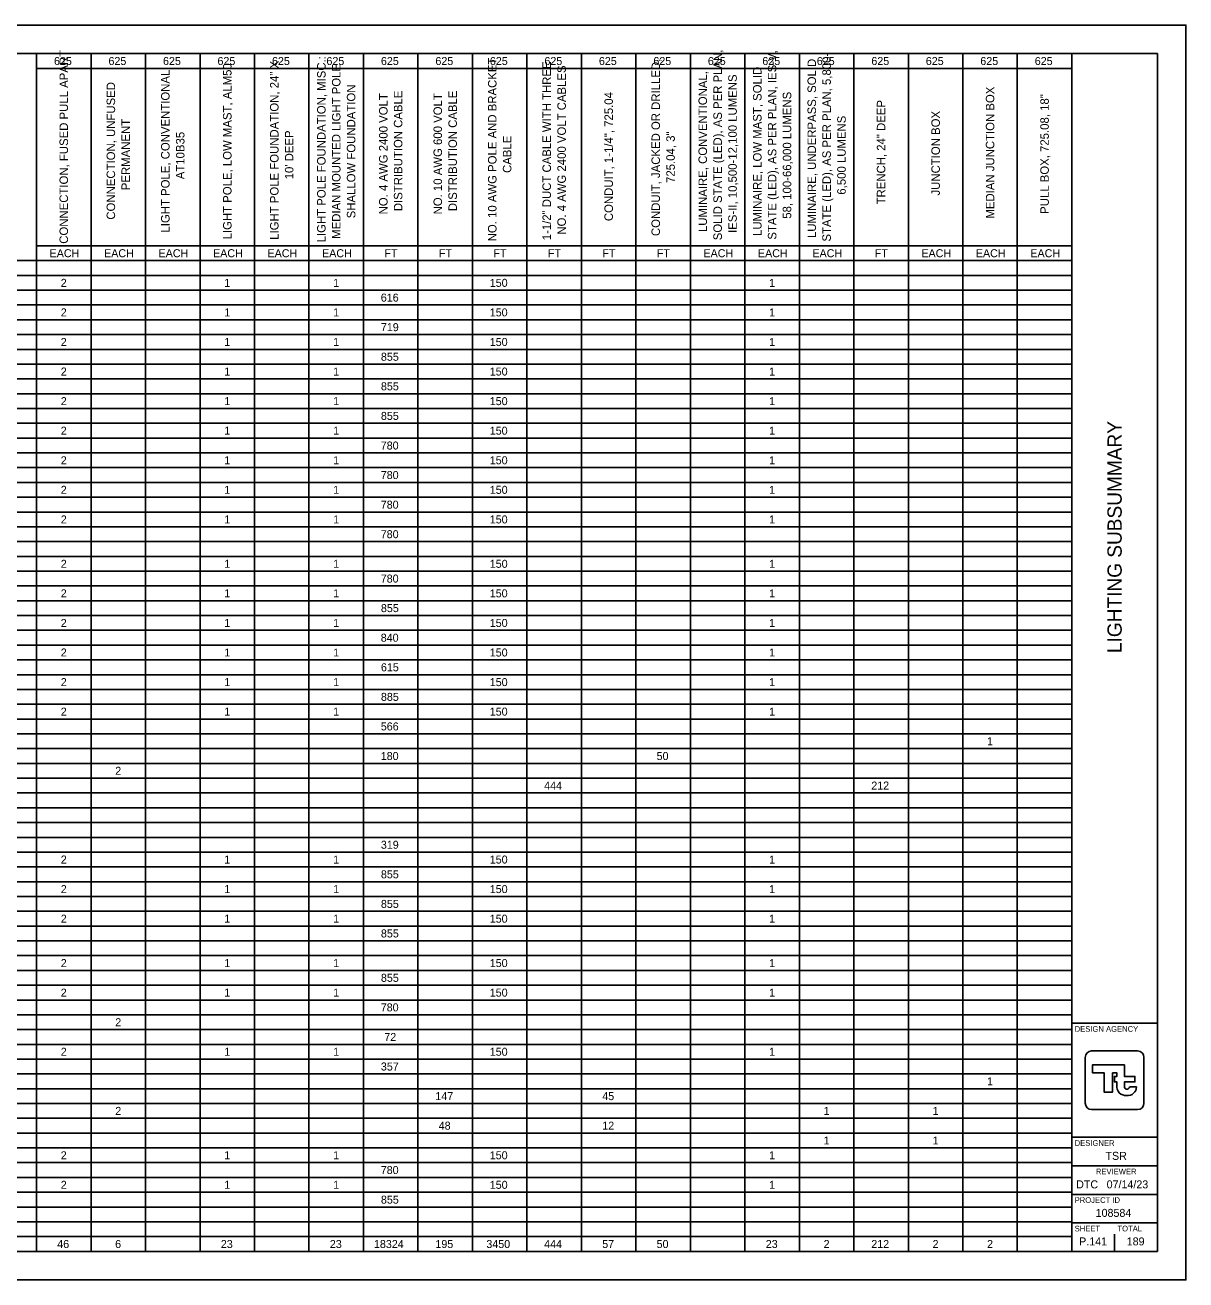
# Model space of a CAD drawing. Extents: x 0 to 34, y 0 to 22.
# Drawn here: x 13.65 to 34, y 0 to 22 of the extents above; entities that cross this region are included whole.
import ezdxf

# ---------------------------------------------------------------- set-up
doc = ezdxf.new("R2010")
doc.units = 0
for name, color, linetype in [('Default', 7, 'Continuous'), ('SH_Border', 7, 'Continuous'), ('SH_Cut_Line', 7, 'Continuous'), ('SH_Data', 7, 'Continuous')]:
    doc.layers.add(name, color=color, linetype=linetype)

msp = doc.modelspace()

# ---------------------------------------------------------------- linework, layer by layer
at = {"layer": 'Default'}
for p, q in [((1.5, 21.5), (32, 21.5)), ((13.852, 21.5), (13.852, 0.5)), ((14.807, 21.5), (14.807, 0.759)), ((15.762, 21.5), (15.762, 0.759)), ((16.718, 21.5), (16.718, 0.759)), ((17.673, 21.5), (17.673, 0.759)), ((18.628, 21.5), (18.628, 0.759)), ((19.583, 21.5), (19.583, 0.759)), ((20.538, 21.5), (20.538, 0.759)), ((21.493, 21.5), (21.493, 0.759)), ((22.449, 21.5), (22.449, 0.759)), ((23.404, 21.5), (23.404, 0.759)), ((24.359, 21.5), (24.359, 0.759)), ((25.314, 21.5), (25.314, 0.759)), ((26.269, 21.5), (26.269, 0.759)), ((27.224, 21.5), (27.224, 0.759)), ((28.179, 21.5), (28.179, 0.759)), ((29.135, 21.5), (29.135, 0.759)), ((30.09, 21.5), (30.09, 0.759)), ((31.045, 21.5), (31.045, 0.759)), ((32, 21.5), (32, 0.759)), ((13.852, 21.241), (32, 21.241)), ((13.852, 18.13), (32, 18.13)), ((1.5, 17.87), (32, 17.87)), ((1.5, 17.611), (32, 17.611)), ((1.5, 17.352), (32, 17.352)), ((1.5, 17.093), (32, 17.093)), ((1.5, 16.833), (32, 16.833)), ((1.5, 16.574), (32, 16.574)), ((1.5, 16.315), (32, 16.315)), ((1.5, 16.056), (32, 16.056)), ((1.5, 15.796), (32, 15.796)), ((1.5, 15.537), (32, 15.537)), ((1.5, 15.278), (32, 15.278)), ((1.5, 15.019), (32, 15.019)), ((1.5, 14.759), (32, 14.759)), ((1.5, 14.5), (32, 14.5)), ((1.5, 14.241), (32, 14.241)), ((1.5, 13.981), (32, 13.981)), ((1.5, 13.722), (32, 13.722)), ((1.5, 13.463), (32, 13.463)), ((1.5, 13.204), (32, 13.204)), ((1.5, 12.944), (32, 12.944)), ((1.5, 12.685), (32, 12.685)), ((1.5, 12.426), (32, 12.426)), ((1.5, 12.167), (32, 12.167)), ((1.5, 11.907), (32, 11.907)), ((1.5, 11.648), (32, 11.648)), ((1.5, 11.389), (32, 11.389)), ((1.5, 11.13), (32, 11.13)), ((1.5, 10.87), (32, 10.87)), ((1.5, 10.611), (32, 10.611)), ((1.5, 10.352), (32, 10.352)), ((1.5, 10.093), (32, 10.093)), ((1.5, 9.833), (32, 9.833)), ((1.5, 9.574), (32, 9.574)), ((1.5, 9.315), (32, 9.315)), ((1.5, 9.056), (32, 9.056)), ((1.5, 8.796), (32, 8.796)), ((1.5, 8.537), (32, 8.537)), ((1.5, 8.278), (32, 8.278)), ((1.5, 8.019), (32, 8.019)), ((1.5, 7.759), (32, 7.759)), ((1.5, 7.5), (32, 7.5)), ((1.5, 7.241), (32, 7.241)), ((1.5, 6.981), (32, 6.981)), ((1.5, 6.722), (32, 6.722)), ((1.5, 6.463), (32, 6.463)), ((1.5, 6.204), (32, 6.204)), ((1.5, 5.944), (32, 5.944)), ((1.5, 5.685), (32, 5.685)), ((1.5, 5.426), (32, 5.426)), ((1.5, 5.167), (32, 5.167)), ((1.5, 4.907), (32, 4.907)), ((1.5, 4.648), (32, 4.648)), ((1.5, 4.389), (32, 4.389)), ((1.5, 4.13), (32, 4.13)), ((1.5, 3.87), (32, 3.87)), ((1.5, 3.611), (32, 3.611)), ((1.5, 3.352), (32, 3.352)), ((1.5, 3.093), (32, 3.093)), ((1.5, 2.833), (32, 2.833)), ((1.5, 2.574), (32, 2.574)), ((1.5, 2.315), (32, 2.315)), ((1.5, 2.056), (32, 2.056)), ((1.5, 1.796), (32, 1.796)), ((1.5, 1.537), (32, 1.537)), ((1.5, 1.278), (32, 1.278)), ((1.5, 1.019), (32, 1.019)), ((1.5, 0.759), (32, 0.759)), ((14.807, 0.759), (14.807, 0.5)), ((15.762, 0.759), (15.762, 0.5)), ((16.718, 0.759), (16.718, 0.5)), ((17.673, 0.759), (17.673, 0.5)), ((18.628, 0.759), (18.628, 0.5)), ((19.583, 0.759), (19.583, 0.5)), ((20.538, 0.759), (20.538, 0.5)), ((21.493, 0.759), (21.493, 0.5)), ((22.449, 0.759), (22.449, 0.5)), ((23.404, 0.759), (23.404, 0.5)), ((24.359, 0.759), (24.359, 0.5)), ((25.314, 0.759), (25.314, 0.5)), ((26.269, 0.759), (26.269, 0.5)), ((27.224, 0.759), (27.224, 0.5)), ((28.179, 0.759), (28.179, 0.5)), ((29.135, 0.759), (29.135, 0.5)), ((30.09, 0.759), (30.09, 0.5)), ((31.045, 0.759), (31.045, 0.5)), ((32, 0.759), (32, 0.5)), ((1.5, 0.5), (32, 0.5))]:
    msp.add_line(p, q, dxfattribs=at)
at = {"layer": 'SH_Border'}
for p, q in [((32, 0.5), (32, 21.5)), ((32, 4.5), (33.5, 4.5)), ((32, 2.5), (33.5, 2.5)), ((32, 2), (33.5, 2)), ((32, 1.5), (33.5, 1.5)), ((32, 1), (33.5, 1))]:
    msp.add_line(p, q, dxfattribs=at)
msp.add_lwpolyline([(1.5, 21.5), (33.5, 21.5), (33.5, 0.5), (1.5, 0.5)], close=True, dxfattribs=at)
at = {"layer": 'SH_Cut_Line'}
msp.add_lwpolyline([(0, 0), (34, 0), (34, 22), (0, 22)], close=True, dxfattribs=at)
at = {"layer": 'SH_Data'}
for p, q in [((32.75, 3.5), (32.75, 3.5)), ((32.791, 3.415), (32.791, 3.415)), ((33.136, 3.385), (33.015, 3.385)), ((32.375, 0.675), (32.375, 0.675)), ((32.75, 0.5), (32.75, 0.8))]:
    msp.add_line(p, q, dxfattribs=at)
for points in [[(32.348, 4.014), (33.152, 4.014)], [(32.236, 3.099), (32.236, 3.901)], [(32.922, 3.399), (32.922, 3.47), (33.107, 3.47), (33.107, 3.568), (32.922, 3.568), (32.922, 3.768), (32.361, 3.768), (32.361, 3.632), (32.566, 3.632), (32.566, 3.294), (32.715, 3.294), (32.715, 3.63), (32.79, 3.63), (32.79, 3.568), (32.748, 3.568), (32.748, 3.47), (32.79, 3.47), (32.79, 3.415), (32.791, 3.415)], [(33.264, 3.901), (33.264, 3.099)], [(33.152, 2.986), (32.348, 2.986)]]:
    msp.add_lwpolyline(points, dxfattribs=at)
for centre, radius, start, end in [((32.348, 3.901), 0.113, 90, 180), ((33.152, 3.901), 0.113, 360, 90), ((32.949, 3.392), 0.16, 171.8856, 274.8323), ((32.968, 3.392), 0.0473, 171.8856, 350.9243), ((32.976, 3.392), 0.16, 265.1677, 357.3201), ((32.348, 3.099), 0.113, 180, 270), ((33.152, 3.099), 0.113, 270, 360)]:
    msp.add_arc(centre, radius, start, end, dxfattribs=at)

# ---------------------------------------------------------------- texts
at = {"layer": 'Default'}
for s, height, p in [('625', 0.1403, (14.158, 21.3)), ('625', 0.1403, (15.113, 21.3)), ('625', 0.1403, (16.069, 21.3)), ('625', 0.1403, (17.024, 21.3)), ('625', 0.1403, (17.979, 21.3)), ('625', 0.1403, (18.934, 21.3)), ('625', 0.1403, (19.889, 21.3)), ('625', 0.1403, (20.844, 21.3)), ('625', 0.1403, (21.799, 21.3)), ('625', 0.1403, (22.755, 21.3)), ('625', 0.1403, (23.71, 21.3)), ('625', 0.1403, (24.665, 21.3)), ('625', 0.1403, (25.62, 21.3)), ('625', 0.1403, (26.575, 21.3)), ('625', 0.1403, (27.53, 21.3)), ('625', 0.1403, (28.486, 21.3)), ('625', 0.1403, (29.441, 21.3)), ('625', 0.1403, (30.396, 21.3)), ('625', 0.1403, (31.351, 21.3)), ('EACH', 0.1403, (14.081, 17.93)), ('EACH', 0.1403, (15.036, 17.93)), ('EACH', 0.1403, (15.991, 17.93)), ('EACH', 0.1403, (16.946, 17.93)), ('EACH', 0.1403, (17.901, 17.93)), ('EACH', 0.1403, (18.857, 17.93)), ('FT', 0.1403, (19.95, 17.93)), ('FT', 0.1403, (20.906, 17.93)), ('FT', 0.1403, (21.861, 17.93)), ('FT', 0.1403, (22.816, 17.93)), ('FT', 0.1403, (23.771, 17.93)), ('FT', 0.1403, (24.726, 17.93)), ('EACH', 0.1403, (25.543, 17.93)), ('EACH', 0.1403, (26.498, 17.93)), ('EACH', 0.1403, (27.453, 17.93)), ('FT', 0.1403, (28.547, 17.93)), ('EACH', 0.1403, (29.363, 17.93)), ('EACH', 0.1403, (30.318, 17.93)), ('EACH', 0.1403, (31.273, 17.93)), ('2', 0.14, (14.277, 17.411)), ('1', 0.14, (17.142, 17.411)), ('1', 0.14, (19.052, 17.411)), ('150', 0.1403, (21.797, 17.411)), ('1', 0.14, (26.694, 17.411)), ('616', 0.1403, (19.887, 17.152)), ('2', 0.14, (14.277, 16.893)), ('1', 0.14, (17.142, 16.893)), ('1', 0.14, (19.052, 16.893)), ('150', 0.1403, (21.797, 16.893)), ('1', 0.14, (26.694, 16.893)), ('719', 0.1403, (19.888, 16.634)), ('2', 0.14, (14.277, 16.374)), ('1', 0.14, (17.142, 16.374)), ('1', 0.14, (19.052, 16.374)), ('150', 0.1403, (21.797, 16.374)), ('1', 0.14, (26.694, 16.374)), ('855', 0.1403, (19.889, 16.115)), ('2', 0.14, (14.277, 15.856)), ('1', 0.14, (17.142, 15.856)), ('1', 0.14, (19.052, 15.856)), ('150', 0.1403, (21.797, 15.856)), ('1', 0.14, (26.694, 15.856)), ('855', 0.1403, (19.889, 15.597)), ('2', 0.14, (14.277, 15.337)), ('1', 0.14, (17.142, 15.337)), ('1', 0.14, (19.052, 15.337)), ('150', 0.1403, (21.797, 15.337)), ('1', 0.14, (26.694, 15.337)), ('855', 0.1403, (19.889, 15.078)), ('2', 0.14, (14.277, 14.819)), ('150', 0.1403, (21.797, 14.819)), ('1', 0.14, (17.142, 14.819)), ('1', 0.14, (19.052, 14.819)), ('1', 0.14, (26.694, 14.819)), ('780', 0.1403, (19.886, 14.559)), ('2', 0.14, (14.277, 14.3)), ('1', 0.14, (17.142, 14.3)), ('1', 0.14, (19.052, 14.3)), ('150', 0.1403, (21.797, 14.3)), ('1', 0.14, (26.694, 14.3)), ('780', 0.1403, (19.886, 14.041)), ('2', 0.14, (14.277, 13.782)), ('1', 0.14, (17.142, 13.782)), ('1', 0.14, (19.052, 13.782)), ('150', 0.1403, (21.797, 13.782)), ('1', 0.14, (26.694, 13.782)), ('780', 0.1403, (19.886, 13.522)), ('2', 0.14, (14.277, 13.263)), ('1', 0.14, (17.142, 13.263)), ('1', 0.14, (19.052, 13.263)), ('150', 0.1403, (21.797, 13.263)), ('1', 0.14, (26.694, 13.263)), ('780', 0.1403, (19.886, 13.004)), ('2', 0.14, (14.277, 12.485)), ('1', 0.14, (17.142, 12.485)), ('1', 0.14, (19.052, 12.485)), ('150', 0.1403, (21.797, 12.485)), ('1', 0.14, (26.694, 12.485)), ('780', 0.1403, (19.886, 12.226)), ('2', 0.14, (14.277, 11.967)), ('1', 0.14, (17.142, 11.967)), ('1', 0.14, (19.052, 11.967)), ('150', 0.1403, (21.797, 11.967)), ('1', 0.14, (26.694, 11.967)), ('855', 0.1403, (19.889, 11.708)), ('2', 0.14, (14.277, 11.448)), ('1', 0.14, (17.142, 11.448)), ('1', 0.14, (19.052, 11.448)), ('150', 0.1403, (21.797, 11.448)), ('1', 0.14, (26.694, 11.448)), ('840', 0.1403, (19.886, 11.189)), ('2', 0.14, (14.277, 10.93)), ('1', 0.14, (17.142, 10.93)), ('1', 0.14, (19.052, 10.93)), ('150', 0.1403, (21.797, 10.93)), ('1', 0.14, (26.694, 10.93)), ('615', 0.1403, (19.889, 10.671)), ('2', 0.14, (14.277, 10.411)), ('1', 0.14, (17.142, 10.411)), ('1', 0.14, (19.052, 10.411)), ('150', 0.1403, (21.797, 10.411)), ('1', 0.14, (26.694, 10.411)), ('885', 0.1403, (19.889, 10.152)), ('2', 0.14, (14.277, 9.893)), ('1', 0.14, (17.142, 9.893)), ('1', 0.14, (19.052, 9.893)), ('150', 0.1403, (21.797, 9.893)), ('1', 0.14, (26.694, 9.893)), ('566', 0.1403, (19.887, 9.634)), ('1', 0.14, (30.514, 9.374)), ('180', 0.1403, (19.886, 9.115)), ('50', 0.1403, (24.722, 9.115)), ('2', 0.14, (15.232, 8.856)), ('444', 0.1403, (22.751, 8.597)), ('212', 0.1403, (28.485, 8.597)), ('319', 0.1403, (19.888, 7.559)), ('2', 0.14, (14.277, 7.3)), ('1', 0.14, (17.142, 7.3)), ('1', 0.14, (19.052, 7.3)), ('150', 0.1403, (21.797, 7.3)), ('1', 0.14, (26.694, 7.3)), ('855', 0.1403, (19.889, 7.041)), ('2', 0.14, (14.277, 6.782)), ('1', 0.14, (17.142, 6.782)), ('1', 0.14, (19.052, 6.782)), ('150', 0.1403, (21.797, 6.782)), ('1', 0.14, (26.694, 6.782)), ('855', 0.1403, (19.889, 6.522)), ('2', 0.14, (14.277, 6.263)), ('1', 0.14, (17.142, 6.263)), ('1', 0.14, (19.052, 6.263)), ('150', 0.1403, (21.797, 6.263)), ('1', 0.14, (26.694, 6.263)), ('855', 0.1403, (19.889, 6.004)), ('2', 0.14, (14.277, 5.485)), ('1', 0.14, (17.142, 5.485)), ('1', 0.14, (19.052, 5.485)), ('150', 0.1403, (21.797, 5.485)), ('1', 0.14, (26.694, 5.485)), ('855', 0.1403, (19.889, 5.226)), ('2', 0.14, (14.277, 4.967)), ('1', 0.14, (17.142, 4.967)), ('1', 0.14, (19.052, 4.967)), ('150', 0.1403, (21.797, 4.967)), ('1', 0.14, (26.694, 4.967)), ('780', 0.1403, (19.886, 4.708)), ('2', 0.14, (15.232, 4.448)), ('72', 0.1403, (19.948, 4.189)), ('2', 0.14, (14.277, 3.93)), ('1', 0.14, (17.142, 3.93)), ('1', 0.14, (19.052, 3.93)), ('150', 0.1403, (21.797, 3.93)), ('1', 0.14, (26.694, 3.93)), ('357', 0.1403, (19.888, 3.671)), ('1', 0.14, (30.514, 3.411)), ('147', 0.1403, (20.843, 3.152)), ('45', 0.1403, (23.769, 3.152)), ('2', 0.14, (15.232, 2.893)), ('1', 0.14, (27.649, 2.893)), ('1', 0.14, (29.559, 2.893)), ('48', 0.1403, (20.902, 2.634)), ('12', 0.1403, (23.769, 2.634)), ('1', 0.14, (27.649, 2.374)), ('1', 0.14, (29.559, 2.374)), ('2', 0.14, (14.277, 2.115)), ('1', 0.14, (17.142, 2.115)), ('1', 0.14, (19.052, 2.115)), ('150', 0.1403, (21.797, 2.115)), ('1', 0.14, (26.694, 2.115)), ('780', 0.1403, (19.886, 1.856)), ('2', 0.14, (14.277, 1.597)), ('1', 0.14, (17.142, 1.597)), ('1', 0.14, (19.052, 1.597)), ('150', 0.1403, (21.797, 1.597)), ('1', 0.14, (26.694, 1.597)), ('855', 0.1403, (19.889, 1.337)), ('46', 0.1403, (14.215, 0.559)), ('6', 0.14, (15.23, 0.559)), ('23', 0.1403, (17.083, 0.559)), ('23', 0.1403, (18.994, 0.559)), ('18324', 0.1403, (19.767, 0.559)), ('195', 0.1403, (20.844, 0.559)), ('3450', 0.1403, (21.737, 0.559)), ('444', 0.1403, (22.751, 0.559)), ('57', 0.1403, (23.768, 0.559)), ('50', 0.1403, (24.722, 0.559)), ('23', 0.1403, (26.635, 0.559)), ('2', 0.14, (27.649, 0.559)), ('212', 0.1403, (28.485, 0.559)), ('2', 0.14, (29.559, 0.559)), ('2', 0.14, (30.514, 0.559))]:
    msp.add_text(s, height=height, dxfattribs=at).set_placement(p)
for s, height, p in [('CONNECTION, FUSED PULL APART', 0.14894, (14.404, 18.166)), ('LIGHT POLE FOUNDATION, 24" X ', 0.14894, (18.094, 18.236)), ('LIGHT POLE FOUNDATION, MISC.: ', 0.14894, (18.919, 18.191)), ('NO. 10 AWG POLE AND BRACKET ', 0.14894, (21.915, 18.209)), ('1-1/2" DUCT CABLE WITH THREE ', 0.14894, (22.87, 18.227)), ('CONDUIT, JACKED OR DRILLED, ', 0.14894, (24.781, 18.301)), ('SOLID STATE (LED), AS PER PLAN, ', 0.14894, (25.866, 18.228)), ('STATE (LED), AS PER PLAN, IES-V, ', 0.14894, (26.821, 18.238)), ('LUMINAIRE, UNDERPASS, SOLID ', 0.14894, (27.516, 18.266)), ('STATE (LED), AS PER PLAN, 5,800-', 0.14894, (27.776, 18.205)), ('LIGHT POLE, CONVENTIONAL, ', 0.14894, (16.184, 18.363)), ('LIGHT POLE, LOW MAST, ALM50', 0.14894, (17.27, 18.243)), ('MEDIAN MOUNTED LIGHT POLE ', 0.14894, (19.18, 18.253)), ('NO. 4 AWG 2400 VOLT CABLES', 0.14894, (23.131, 18.326)), ('LUMINAIRE, CONVENTIONAL, ', 0.14894, (25.605, 18.371)), ('IES-II, 10,500-12,100 LUMENS', 0.14894, (26.127, 18.356)), ('LUMINAIRE, LOW MAST, SOLID ', 0.14894, (26.561, 18.303)), ('CONNECTION, UNFUSED ', 0.14894, (15.229, 18.589)), ('SHALLOW FOUNDATION', 0.14894, (19.441, 18.612)), ('MEDIAN JUNCTION BOX', 0.14894, (30.642, 18.608)), ('NO. 4 AWG 2400 VOLT ', 0.14894, (20.005, 18.681)), ('DISTRIBUTION CABLE', 0.14894, (20.265, 18.738)), ('NO. 10 AWG 600 VOLT ', 0.14894, (20.96, 18.681)), ('DISTRIBUTION CABLE', 0.14894, (21.221, 18.738)), ('CONDUIT, 1-1/4", 725.04', 0.14894, (23.956, 18.563)), ('58, 100-66,000 LUMENS', 0.14894, (27.082, 18.605)), ('PULL BOX, 725.08, 18"', 0.14894, (31.597, 18.691)), ('TRENCH, 24" DEEP', 0.14894, (28.731, 18.856)), ('JUNCTION BOX', 0.14894, (29.687, 19.012)), ('PERMANENT', 0.1489, (15.49, 19.106)), ('6,500 LUMENS', 0.14894, (28.037, 19.027)), ('AT10B35', 0.1489, (16.445, 19.298)), ("10' DEEP", 0.1489, (18.355, 19.296)), ('CABLE', 0.1489, (22.176, 19.408)), ('725.04, 3"', 0.1489, (25.041, 19.233))]:
    msp.add_text(s, height=height, rotation=90, dxfattribs=at).set_placement(p)
at = {"layer": 'SH_Data'}
msp.add_text('LIGHTING SUBSUMMARY', height=0.25, rotation=90, dxfattribs=at).set_placement((32.875, 10.99))
for s, height, p in [('DESIGN AGENCY', 0.1, (32.05, 4.35)), ('DESIGNER', 0.1, (32.05, 2.35)), ('TSR', 0.14, (32.59, 2.105)), ('REVIEWER', 0.1, (32.422, 1.85)), ('DTC', 0.14, (32.076, 1.605)), ('07/14/23', 0.14, (32.611, 1.605)), ('PROJECT ID', 0.1, (32.05, 1.35)), ('108584', 0.14, (32.418, 1.105)), ('SHEET', 0.1, (32.05, 0.85)), ('TOTAL', 0.1, (32.8, 0.85)), ('P.141', 0.14, (32.129, 0.605)), ('189', 0.14, (32.963, 0.605))]:
    msp.add_text(s, height=height, dxfattribs=at).set_placement(p)

doc.saveas('drawing.dxf')
